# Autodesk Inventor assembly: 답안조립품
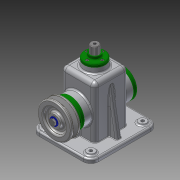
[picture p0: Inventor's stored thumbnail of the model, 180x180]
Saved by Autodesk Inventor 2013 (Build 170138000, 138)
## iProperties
Created: 2016-01
Part Number: 답안조립품
Document SubType Name: Assembly
Designer: User
Author: User
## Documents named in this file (19)
- C:\Users\User\Desktop\460126V1013\답안조립품.iam
- C:\Users\User\Desktop\460126V1013\본체.ipt
- C:\Users\User\Desktop\460126V1013\편심축.ipt
- C:\Users\User\Desktop\460126V1013\키 5 x 5 x 14.ipt
- C:\Users\User\Desktop\460126V1013\베어링 15 x 35 x 11.ipt
- C:\Users\User\Desktop\460126V1013\멈춤링 15 x 1.ipt
- C:\Users\User\Desktop\460126V1013\뒤커버.ipt
- C:\Users\User\Desktop\460126V1013\앞커버.ipt
- C:\Users\User\Desktop\460126V1013\볼트 M4 x 10.ipt
- C:\Users\User\Desktop\460126V1013\V-벨트풀리.ipt
- C:\Users\User\Desktop\460126V1013\오일실 15 25 7.ipt
- C:\Users\User\Desktop\460126V1013\슬라이드바.ipt
- C:\Users\User\Desktop\460126V1013\볼트 M6 x 12.ipt
- C:\Users\User\Desktop\460126V1013\상부부시.ipt
- C:\Users\User\Desktop\460126V1013\볼트 M3 x 8.ipt
- C:\Users\User\Desktop\460126V1013\링크.ipt
- C:\Users\User\Desktop\460126V1013\고정핀.ipt
- C:\Users\User\Desktop\460126V1013\멈춤링 6 x 5.ipt
- C:\Users\User\Desktop\460126V1013\와셔.ipt
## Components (15 placed, 5 different names)
1. V-벨트풀리:1 — 각도:1, 각도:3
2. 고정핀:1
3. ISO 4018 M6 x 12:1 — 각도:6
4. ISO 4762 M4 x 10:2
5. ISO 4762 M4 x 10:3
6. ISO 4762 M4 x 10:4
7. ISO 4762 M4 x 10:5
8. ISO 4762 M4 x 10:1
9. ISO 4762 M4 x 10:6
10. ISO 4762 M4 x 10:7
11. ISO 4762 M4 x 10:8
12. ISO 4762 M3 x 8:1
13. ISO 4762 M3 x 8:2
14. ISO 4762 M3 x 8:3
15. ISO 4762 M3 x 8:4
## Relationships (3: Angle 3)
- 각도:1 [Angle]: V-벨트풀리:1
- 각도:3 [Angle]: V-벨트풀리:1
- 각도:6 [Angle]: ISO 4018 M6 x 12:1
